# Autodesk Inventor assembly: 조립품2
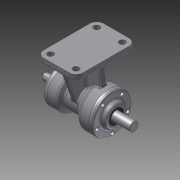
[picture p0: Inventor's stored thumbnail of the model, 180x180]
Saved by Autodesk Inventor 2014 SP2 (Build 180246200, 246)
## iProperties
Created: 2015-08
Part Number: 조립품2
Document SubType Name: Assembly
Designer: 이준우
Author: 이준우
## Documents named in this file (9)
- C:\Users\201-14\Desktop\450805V1041\조립품2.iam
- C:\Users\201-14\Desktop\450805V1041\본체.ipt
- C:\Users\201-14\Desktop\450805V1041\축.ipt
- C:\Users\201-14\Desktop\450805V1041\베어링 6203.ipt
- C:\Users\201-14\Desktop\450805V1041\베어링 6205.ipt
- C:\Users\201-14\Desktop\450805V1041\뒤커버.ipt
- C:\Users\201-14\Desktop\450805V1041\앞커버.ipt
- C:\Users\201-14\Desktop\450805V1041\오일실 .ipt
- 오일실 .ipt
